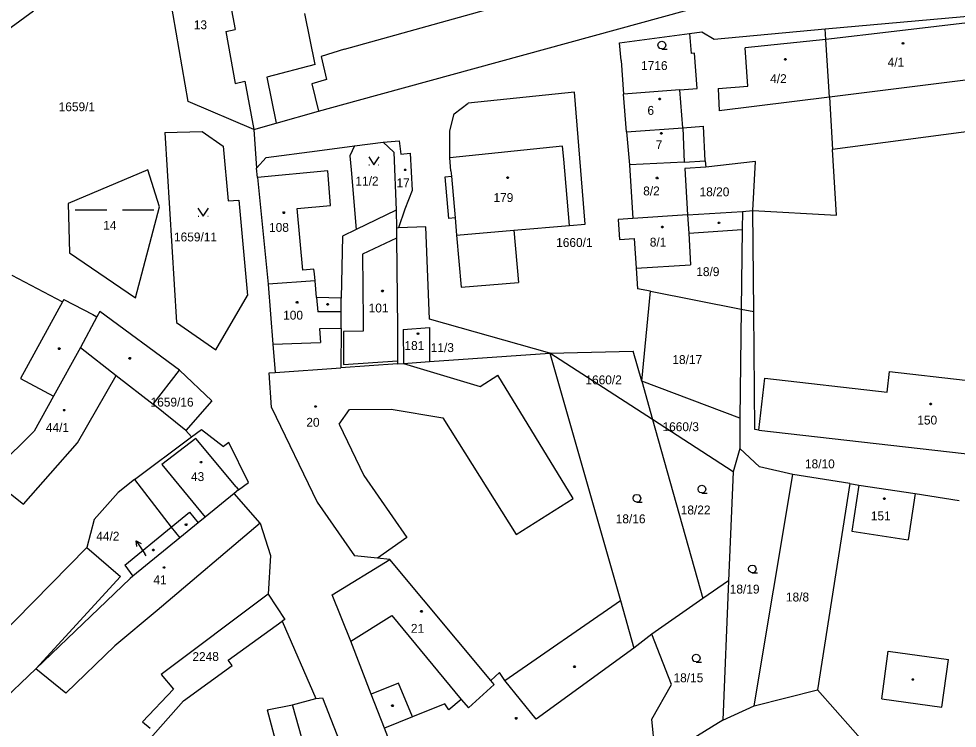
# Model space of a CAD drawing. Extents: x -802857 to -799647, y -1020285 to -1015884.
# Drawn here: x -801501.8 to -801322.5, y -1017775.9 to -1017640.2 of the extents above; entities that cross this region are included whole.
import ezdxf

# ---------------------------------------------------------------- set-up
doc = ezdxf.new("R2010")
doc.units = 0
for name, color, linetype in [('Default', 7, 'Continuous'), ('KN_HRANICE', 7, 'Continuous'), ('KN_KULTURY', 7, 'Continuous'), ('KN_PARCELY', 7, 'Continuous'), ('KN_SLUCKY', 7, 'Continuous')]:
    doc.layers.add(name, color=color, linetype=linetype)

# ---------------------------------------------------------------- blocks, each defined once
blk = doc.blocks.new('304')
at = {"layer": 'Default'}
blk.add_lwpolyline([(0, 0), (-0.38, 0.1), (-0.65, 0.37), (-0.75, 0.74), (-0.65, 1.11), (-0.38, 1.38), (-0.01, 1.48), (0.36, 1.38), (0.63, 1.11), (0.73, 0.73), (0.63, 0.35), (0.36, 0.08), (-0.02, -0.02), (0.98, -0.02)], dxfattribs=at)
blk = doc.blocks.new('314')
at = {"layer": 'Default'}
for p, q in [((-0.95, 0), (-0.85, 0)), ((0.85, 0), (0.95, 0))]:
    blk.add_line(p, q, dxfattribs=at)
blk.add_lwpolyline([(-1, 1.5), (0, 0), (1, 1.5)], dxfattribs=at)
blk = doc.blocks.new('NAHRADNI_SYMBOL')
at = {"layer": 'Default'}
blk.add_lwpolyline([(0.09, 0.15), (0.18, 0), (0.09, -0.15), (-0.09, -0.15), (-0.18, 0), (-0.09, 0.15), (0.09, 0.15)], dxfattribs=at)
blk = doc.blocks.new('803')
at = {"layer": 'Default'}
for p, q in [((-7.5, 0), (-1.5, 0)), ((1.5, 0), (7.5, 0))]:
    blk.add_line(p, q, dxfattribs=at)
blk = doc.blocks.new('10292')
at = {"layer": 'Default'}
blk.add_line((0, 3), (0, 0), dxfattribs=at)
blk.add_lwpolyline([(-0.5, 2), (0, 3), (0.5, 2)], dxfattribs=at)
blk = doc.blocks.new('402')
at = {"layer": 'Default'}
blk.add_lwpolyline([(0.09, 0.15), (0.18, 0), (0.09, -0.15), (-0.09, -0.15), (-0.18, 0), (-0.09, 0.15), (0.09, 0.15)], dxfattribs=at)

msp = doc.modelspace()

# ---------------------------------------------------------------- linework, layer by layer
at = {"layer": 'KN_HRANICE'}
for p, q in [((-801439.56, -1017646.05), (-801339.49, -1017618.1)), ((-801464.55, -1017620.59), (-801460.47, -1017642.27)), ((-801469.47, -1017656.08), (-801475.13, -1017623.23)), ((-801436.88, -1017655.78), (-801344.28, -1017630.37)), ((-801499.03, -1017638.78), (-801510.49, -1017647.16)), ((-801445.17, -1017648.98), (-801447.15, -1017639.26)), ((-801347.72, -1017642.2), (-801317.19, -1017639.44)), ((-801368.91, -1017644.12), (-801347.72, -1017642.2)), ((-801347.58, -1017644.22), (-801347.72, -1017642.2)), ((-801462.26, -1017642.67), (-801460.47, -1017642.27)), ((-801462.26, -1017642.67), (-801460.46, -1017652.61)), ((-801387, -1017644.83), (-801373.65, -1017643.04)), ((-801373.65, -1017643.04), (-801371.28, -1017642.72)), ((-801373.65, -1017643.04), (-801373.36, -1017646.87)), ((-801371.28, -1017642.72), (-801368.91, -1017644.12)), ((-801386.74, -1017648.25), (-801387, -1017644.83)), ((-801346.88, -1017655.22), (-801347.58, -1017644.22)), ((-801439.56, -1017646.05), (-801444.04, -1017647.45)), ((-801444.04, -1017647.45), (-801443.02, -1017651.83)), ((-801372.67, -1017646.8), (-801373.36, -1017646.87)), ((-801372.17, -1017653.55), (-801372.67, -1017646.8)), ((-801445.17, -1017648.98), (-801454.4, -1017651.38)), ((-801386.74, -1017648.25), (-801386.24, -1017654.63)), ((-801460.46, -1017652.61), (-801458.6, -1017652.2)), ((-801458.6, -1017652.2), (-801456.87, -1017661.39)), ((-801454.4, -1017651.38), (-801452.65, -1017660.21)), ((-801443.02, -1017651.83), (-801445.83, -1017652.69)), ((-801445.83, -1017652.69), (-801444.54, -1017657.93)), ((-801395.62, -1017654.26), (-801415.94, -1017656.38)), ((-801393.58, -1017679.48), (-801395.62, -1017654.26)), ((-801375.49, -1017653.85), (-801386.24, -1017654.63)), ((-801385.72, -1017661.85), (-801386.24, -1017654.63)), ((-801375.49, -1017653.85), (-801372.17, -1017653.55)), ((-801374.94, -1017661.08), (-801375.49, -1017653.85)), ((-801456.87, -1017661.39), (-801469.47, -1017656.08)), ((-801444.54, -1017657.93), (-801436.88, -1017655.78)), ((-801418.65, -1017658.44), (-801415.94, -1017656.38)), ((-801346.88, -1017655.22), (-801346.31, -1017665.23)), ((-801452.65, -1017660.21), (-801444.54, -1017657.93)), ((-801419.45, -1017661.66), (-801418.65, -1017658.44)), ((-801473.9, -1017661.96), (-801466.75, -1017661.81)), ((-801466.75, -1017661.81), (-801462.75, -1017664.58)), ((-801456.87, -1017661.39), (-801452.65, -1017660.21)), ((-801456.87, -1017661.39), (-801456.38, -1017668.8)), ((-801419.44, -1017665.46), (-801419.45, -1017661.66)), ((-801385.72, -1017661.85), (-801374.94, -1017661.08)), ((-801385.72, -1017661.85), (-801385.15, -1017668.16)), ((-801374.94, -1017661.08), (-801371.01, -1017660.78)), ((-801370.64, -1017667.41), (-801371.01, -1017660.78)), ((-801314.72, -1017661.03), (-801346.31, -1017665.23)), ((-801473.9, -1017661.96), (-801471.67, -1017698.28)), ((-801432.19, -1017663.81), (-801429.11, -1017663.56)), ((-801429.11, -1017663.56), (-801428.81, -1017666.12)), ((-801462.75, -1017664.58), (-801461.83, -1017675.05)), ((-801454.57, -1017666.75), (-801444.82, -1017665.47)), ((-801444.82, -1017665.47), (-801437.64, -1017664.53)), ((-801437.64, -1017664.53), (-801438.53, -1017666.45)), ((-801437.64, -1017664.53), (-801432.19, -1017663.81)), ((-801432.19, -1017663.81), (-801430.14, -1017665.75)), ((-801419.44, -1017666.81), (-801419.44, -1017665.46)), ((-801345.56, -1017677.77), (-801346.31, -1017665.23)), ((-801456.38, -1017668.8), (-801454.57, -1017666.75)), ((-801438.53, -1017666.45), (-801438.3, -1017669.15)), ((-801430.14, -1017665.75), (-801429.73, -1017676.83)), ((-801428.81, -1017666.12), (-801427.01, -1017665.96)), ((-801427.01, -1017665.96), (-801426.65, -1017673.07)), ((-801419.23, -1017669.3), (-801419.44, -1017666.81)), ((-801477.13, -1017669.12), (-801492.36, -1017675.58)), ((-801474.9, -1017676.19), (-801477.13, -1017669.12)), ((-801456.2, -1017670.59), (-801456.38, -1017668.8)), ((-801374.65, -1017667.67), (-801385.15, -1017668.16)), ((-801385.15, -1017668.16), (-801384.5, -1017678.44)), ((-801374.65, -1017667.67), (-801370.64, -1017667.41)), ((-801370.54, -1017668.61), (-801374.57, -1017668.87)), ((-801374.57, -1017668.87), (-801374.01, -1017677.75)), ((-801370.64, -1017667.41), (-801370.54, -1017668.61)), ((-801361.03, -1017667.51), (-801370.54, -1017668.61)), ((-801361.54, -1017676.89), (-801361.03, -1017667.51)), ((-801456.2, -1017670.59), (-801454.16, -1017690.99)), ((-801438.3, -1017669.15), (-801437.35, -1017680.56)), ((-801420.34, -1017670.46), (-801419.14, -1017670.36)), ((-801419.66, -1017678.43), (-801420.34, -1017670.46)), ((-801419.23, -1017669.3), (-801419.14, -1017670.36)), ((-801426.65, -1017673.07), (-801428.05, -1017676.64)), ((-801492.36, -1017675.58), (-801492.13, -1017684.97)), ((-801479.51, -1017693.58), (-801474.9, -1017676.19)), ((-801461.83, -1017675.05), (-801459.74, -1017674.9)), ((-801459.74, -1017674.9), (-801458.13, -1017693.12)), ((-801429.73, -1017676.83), (-801437.35, -1017680.56)), ((-801429.73, -1017676.83), (-801429.65, -1017680.25)), ((-801428.05, -1017676.64), (-801429.23, -1017680.23)), ((-801374.01, -1017677.75), (-801384.5, -1017678.44)), ((-801374.01, -1017677.75), (-801363.53, -1017677.06)), ((-801363.53, -1017677.06), (-801361.54, -1017676.89)), ((-801361.37, -1017696.22), (-801361.54, -1017676.89)), ((-801361.54, -1017676.89), (-801345.56, -1017677.77)), ((-801418.46, -1017678.33), (-801419.66, -1017678.43)), ((-801418.46, -1017678.33), (-801418.18, -1017681.62)), ((-801407.22, -1017680.67), (-801396.57, -1017679.74)), ((-801396.57, -1017679.74), (-801393.58, -1017679.48)), ((-801384.5, -1017678.44), (-801387.29, -1017678.62)), ((-801387.29, -1017678.62), (-801387.04, -1017682.41)), ((-801437.35, -1017680.56), (-801439.98, -1017681.83)), ((-801429.23, -1017680.23), (-801429.65, -1017680.25)), ((-801429.65, -1017680.25), (-801429.62, -1017682.21)), ((-801424.02, -1017680.04), (-801429.23, -1017680.23)), ((-801423.35, -1017697.69), (-801424.02, -1017680.04)), ((-801418.18, -1017681.62), (-801417.31, -1017691.58)), ((-801407.22, -1017680.67), (-801406.35, -1017690.63)), ((-801373.8, -1017681.22), (-801363.58, -1017680.51)), ((-801373.8, -1017681.22), (-801373.44, -1017687.26)), ((-801363.58, -1017680.51), (-801363.78, -1017695.75)), ((-801439.98, -1017681.83), (-801440.22, -1017693.66)), ((-801429.62, -1017682.21), (-801429.47, -1017699.34)), ((-801387.04, -1017682.41), (-801384.25, -1017682.23)), ((-801384.25, -1017682.23), (-801383.87, -1017687.92)), ((-801492.13, -1017684.97), (-801479.51, -1017693.58)), ((-801383.87, -1017687.92), (-801373.44, -1017687.26)), ((-801383.87, -1017687.92), (-801383.61, -1017691.85)), ((-801503.16, -1017689.24), (-801493.48, -1017694.38)), ((-801445.17, -1017690.35), (-801454.16, -1017690.99)), ((-801444.9, -1017693.53), (-801445.17, -1017690.35)), ((-801417.31, -1017691.58), (-801406.35, -1017690.63)), ((-801454.16, -1017690.99), (-801453.25, -1017702.44)), ((-801381.12, -1017692.34), (-801383.61, -1017691.85)), ((-801382.78, -1017709.52), (-801381.12, -1017692.34)), ((-801381.12, -1017692.34), (-801363.78, -1017695.75)), ((-801493.2, -1017693.88), (-801493.48, -1017694.38)), ((-801493.2, -1017693.88), (-801487.66, -1017696.81)), ((-801464.13, -1017703.51), (-801458.13, -1017693.12)), ((-801444.9, -1017693.53), (-801444.66, -1017696.24)), ((-801440.21, -1017696.24), (-801440.22, -1017693.66)), ((-801363.78, -1017695.75), (-801364.05, -1017716.58)), ((-801363.78, -1017695.75), (-801361.37, -1017696.22)), ((-801486.87, -1017697.21), (-801490.05, -1017703.09)), ((-801487.66, -1017696.81), (-801486.87, -1017697.21)), ((-801486.33, -1017696.21), (-801486.87, -1017697.21)), ((-801471.12, -1017707.39), (-801486.33, -1017696.21)), ((-801440.21, -1017696.24), (-801444.66, -1017696.24)), ((-801440.22, -1017698), (-801440.21, -1017696.24)), ((-801400.33, -1017704.19), (-801423.35, -1017697.69)), ((-801361.18, -1017718.78), (-801361.37, -1017696.22)), ((-801471.67, -1017698.28), (-801464.13, -1017703.51)), ((-801440.23, -1017699.44), (-801440.25, -1017706.98)), ((-801440.23, -1017699.44), (-801440.22, -1017698)), ((-801429.47, -1017699.34), (-801429.43, -1017705.64)), ((-801428.36, -1017699.63), (-801423.34, -1017699.29)), ((-801423.34, -1017699.29), (-801423.32, -1017705.79)), ((-801428.36, -1017699.63), (-801428.32, -1017706.16)), ((-801490.05, -1017703.09), (-801495.16, -1017712.38)), ((-801453.25, -1017702.44), (-801452.8, -1017707.85)), ((-801423.32, -1017705.79), (-801400.33, -1017704.19)), ((-801400.33, -1017704.19), (-801384.4, -1017703.77)), ((-801400.33, -1017704.19), (-801386.84, -1017751.44)), ((-801380.71, -1017716.88), (-801400.33, -1017704.19)), ((-801382.78, -1017709.52), (-801384.4, -1017703.77)), ((-801429.43, -1017706.24), (-801440.25, -1017706.98)), ((-801429.43, -1017705.64), (-801429.43, -1017706.24)), ((-801429.43, -1017706.24), (-801428.32, -1017706.16)), ((-801428.32, -1017706.16), (-801423.32, -1017705.79)), ((-801476.12, -1017713.95), (-801471.12, -1017707.39)), ((-801471.12, -1017707.39), (-801464.92, -1017713.27)), ((-801453.96, -1017707.92), (-801452.8, -1017707.85)), ((-801453.53, -1017714.55), (-801453.96, -1017707.92)), ((-801452.8, -1017707.85), (-801440.25, -1017706.98)), ((-801364.05, -1017716.58), (-801382.78, -1017709.52)), ((-801382.78, -1017709.52), (-801380.71, -1017716.88)), ((-801495.16, -1017712.38), (-801498.85, -1017719.1)), ((-801469.89, -1017718.97), (-801476.12, -1017713.95)), ((-801464.92, -1017713.27), (-801469.89, -1017718.97)), ((-801453.53, -1017714.55), (-801444.8, -1017732.63)), ((-801365.33, -1017726.83), (-801380.71, -1017716.88)), ((-801380.71, -1017716.88), (-801371.09, -1017751.09)), ((-801364.05, -1017716.58), (-801364.06, -1017722.39)), ((-801498.85, -1017719.1), (-801507.61, -1017727.7)), ((-801469.89, -1017718.97), (-801468.81, -1017720.17)), ((-801468.81, -1017720.17), (-801466.92, -1017718.75)), ((-801466.92, -1017718.75), (-801462.68, -1017722.04)), ((-801360.4, -1017718.86), (-801361.18, -1017718.78)), ((-801360.4, -1017718.86), (-801315.22, -1017724.02)), ((-801479.69, -1017728.34), (-801468.81, -1017720.17)), ((-801461.67, -1017721.24), (-801462.68, -1017722.04)), ((-801457.95, -1017728.92), (-801461.67, -1017721.24)), ((-801364.06, -1017722.39), (-801365.33, -1017726.83)), ((-801360.25, -1017725.9), (-801364.06, -1017722.39)), ((-801353.93, -1017727.34), (-801360.25, -1017725.9)), ((-801365.33, -1017726.83), (-801366.23, -1017747.72)), ((-801361.29, -1017771.58), (-801353.93, -1017727.34)), ((-801342.99, -1017729.09), (-801353.93, -1017727.34)), ((-801479.69, -1017728.34), (-801482.8, -1017730.8)), ((-801479.69, -1017728.34), (-801472.69, -1017737.41)), ((-801459.8, -1017730.31), (-801457.95, -1017728.92)), ((-801342.99, -1017729.09), (-801349.19, -1017768.52)), ((-801342.99, -1017729.09), (-801341.32, -1017729.38)), ((-801341.32, -1017729.38), (-801330.53, -1017731.02)), ((-801482.8, -1017730.8), (-801487.38, -1017735.95)), ((-801460.64, -1017731), (-801466.21, -1017735.54)), ((-801459.8, -1017730.31), (-801460.64, -1017731)), ((-801455.66, -1017736.67), (-801460.64, -1017731)), ((-801330.53, -1017731.02), (-801322.14, -1017732.32)), ((-801444.8, -1017732.63), (-801437.69, -1017742.9)), ((-801487.38, -1017735.95), (-801488.83, -1017741.31)), ((-801467.55, -1017736.63), (-801471.07, -1017739.5)), ((-801466.21, -1017735.54), (-801467.55, -1017736.63)), ((-801455.66, -1017736.67), (-801453.7, -1017742.86)), ((-801472.69, -1017737.41), (-801471.07, -1017739.5)), ((-801471.07, -1017739.5), (-801480.05, -1017746.82)), ((-801488.83, -1017741.31), (-801482.4, -1017746.87)), ((-801453.7, -1017742.86), (-801454.14, -1017750.26)), ((-801441.93, -1017750.37), (-801430.91, -1017743.61)), ((-801433.27, -1017743.36), (-801437.69, -1017742.9)), ((-801430.91, -1017743.61), (-801433.27, -1017743.36)), ((-801411.64, -1017766.72), (-801430.91, -1017743.61)), ((-801482.4, -1017746.87), (-801498.56, -1017764.53)), ((-801480.55, -1017747.22), (-801498.56, -1017764.53)), ((-801480.05, -1017746.82), (-801480.55, -1017747.22)), ((-801366.23, -1017747.72), (-801371.09, -1017751.09)), ((-801366.23, -1017747.72), (-801367.27, -1017774.31)), ((-801454.14, -1017750.26), (-801474.58, -1017765.6)), ((-801454.14, -1017750.26), (-801451, -1017755.07)), ((-801438.38, -1017759.22), (-801441.93, -1017750.37)), ((-801386.84, -1017751.44), (-801384.3, -1017760.57)), ((-801371.09, -1017751.09), (-801380.85, -1017757.91)), ((-801451, -1017755.07), (-801451.46, -1017755.42)), ((-801451.46, -1017755.42), (-801445.03, -1017770.19)), ((-801380.85, -1017757.91), (-801384.3, -1017760.57)), ((-801377.08, -1017767.48), (-801380.85, -1017757.91)), ((-801434.46, -1017769.34), (-801438.38, -1017759.22)), ((-801384.3, -1017760.57), (-801402.96, -1017774.15)), ((-801498.56, -1017764.53), (-801505.81, -1017771.41)), ((-801474.58, -1017765.6), (-801472.28, -1017768.42)), ((-801409.95, -1017765.22), (-801411.64, -1017766.72)), ((-801408.92, -1017766.74), (-801409.95, -1017765.22)), ((-801415.89, -1017771.96), (-801410.96, -1017767.53)), ((-801410.96, -1017767.53), (-801411.64, -1017766.72)), ((-801402.96, -1017774.15), (-801408.92, -1017766.74)), ((-801380.85, -1017774.15), (-801377.08, -1017767.48)), ((-801472.28, -1017768.42), (-801478.17, -1017774.62)), ((-801431.94, -1017775.86), (-801434.46, -1017769.34)), ((-801361.29, -1017771.58), (-801349.19, -1017768.52)), ((-801338.75, -1017780.31), (-801349.19, -1017768.52)), ((-801449.49, -1017771.37), (-801445.03, -1017770.19)), ((-801445.03, -1017770.19), (-801443.81, -1017770.05)), ((-801443.81, -1017770.05), (-801439.99, -1017779.67)), ((-801420.38, -1017771.18), (-801426.59, -1017773.69)), ((-801419.61, -1017772.37), (-801420.38, -1017771.18)), ((-801417.3, -1017770.37), (-801419.61, -1017772.37)), ((-801417.3, -1017770.37), (-801415.89, -1017771.96)), ((-801454.34, -1017772.35), (-801449.49, -1017771.37)), ((-801454.34, -1017772.35), (-801451.15, -1017784.39)), ((-801367.27, -1017774.31), (-801361.29, -1017771.58)), ((-801478.17, -1017774.62), (-801476.71, -1017775.88)), ((-801426.59, -1017773.69), (-801431.94, -1017775.86)), ((-801380.06, -1017782.2), (-801380.85, -1017774.15)), ((-801367.27, -1017774.31), (-801380.06, -1017782.2)), ((-801428.76, -1017784.1), (-801431.94, -1017775.86))]:
    msp.add_line(p, q, dxfattribs=at)
msp.add_lwpolyline([(-801480.11, -1017781.68), (-801470.32, -1017770.64), (-801461.06, -1017763.9), (-801461.81, -1017762.88), (-801451.46, -1017755.42)], dxfattribs=at)
at = {"layer": 'KN_PARCELY'}
msp.add_line((-801477.47, -1017742.93), (-801477.73, -1017742.53), dxfattribs=at)
at = {"layer": 'KN_SLUCKY'}
for p, q in [((-801317.18, -1017640.62), (-801334.53, -1017642.7)), ((-801334.53, -1017642.7), (-801347.58, -1017644.22)), ((-801347.58, -1017644.22), (-801363.02, -1017645.81)), ((-801362.49, -1017653.14), (-801363.02, -1017645.81)), ((-801315.88, -1017651.33), (-801346.88, -1017655.22)), ((-801368.2, -1017653.58), (-801362.49, -1017653.14)), ((-801368.2, -1017653.58), (-801367.99, -1017657.86)), ((-801346.88, -1017655.22), (-801367.99, -1017657.86)), ((-801374.94, -1017661.08), (-801374.65, -1017667.67)), ((-801397.89, -1017664.58), (-801419.44, -1017666.81)), ((-801397.68, -1017667.07), (-801397.89, -1017664.58)), ((-801396.57, -1017679.74), (-801397.68, -1017667.07)), ((-801442.79, -1017669.32), (-801456.2, -1017670.59)), ((-801442.23, -1017675.92), (-801442.79, -1017669.32)), ((-801419.14, -1017670.36), (-801418.46, -1017678.33)), ((-801448.61, -1017676.52), (-801442.23, -1017675.92)), ((-801447.51, -1017688.29), (-801448.61, -1017676.52)), ((-801374.01, -1017677.75), (-801373.8, -1017681.22)), ((-801363.53, -1017677.06), (-801363.58, -1017680.51)), ((-801418.18, -1017681.62), (-801407.22, -1017680.67)), ((-801429.62, -1017682.21), (-801436.16, -1017685.24)), ((-801436.16, -1017685.24), (-801436.01, -1017697.99)), ((-801445.41, -1017688.09), (-801447.51, -1017688.29)), ((-801445.33, -1017688.99), (-801445.41, -1017688.09)), ((-801445.17, -1017690.35), (-801445.33, -1017688.99)), ((-801440.22, -1017693.66), (-801444.9, -1017693.53)), ((-801493.48, -1017694.38), (-801501.51, -1017709.02)), ((-801440.23, -1017699.44), (-801444.38, -1017699.5)), ((-801444.38, -1017699.5), (-801444.15, -1017702.13)), ((-801436.01, -1017697.99), (-801435.99, -1017699.99)), ((-801435.99, -1017699.99), (-801439.78, -1017700.01)), ((-801439.78, -1017700.01), (-801439.74, -1017706.34)), ((-801490.05, -1017703.09), (-801483.23, -1017708.46)), ((-801453.25, -1017702.44), (-801444.15, -1017702.13)), ((-801439.74, -1017706.34), (-801429.43, -1017705.64)), ((-801428.32, -1017706.16), (-801413.65, -1017710.55)), ((-801490.57, -1017721.33), (-801483.23, -1017708.46)), ((-801483.23, -1017708.46), (-801476.12, -1017713.95)), ((-801413.65, -1017710.55), (-801410.25, -1017708.4)), ((-801395.86, -1017731.97), (-801410.25, -1017708.4)), ((-801335.87, -1017711.65), (-801335.42, -1017707.67)), ((-801335.42, -1017707.67), (-801320.96, -1017709.32)), ((-801501.51, -1017709.02), (-801495.16, -1017712.38)), ((-801360.4, -1017718.86), (-801359.27, -1017708.97)), ((-801359.27, -1017708.97), (-801335.87, -1017711.65)), ((-801440.62, -1017717.72), (-801438.64, -1017714.97)), ((-801438.64, -1017714.97), (-801430.65, -1017714.89)), ((-801430.65, -1017714.89), (-801420.77, -1017716.55)), ((-801420.77, -1017716.55), (-801406.77, -1017738.86)), ((-801440.62, -1017717.72), (-801435.87, -1017727.56)), ((-801468, -1017720.51), (-801474.46, -1017725.46)), ((-801460.29, -1017729.75), (-801468, -1017720.51)), ((-801500.92, -1017733.04), (-801490.57, -1017721.33)), ((-801474.46, -1017725.46), (-801466.21, -1017735.54)), ((-801507.61, -1017727.7), (-801500.92, -1017733.04)), ((-801435.87, -1017727.56), (-801427.66, -1017739.42)), ((-801460.29, -1017729.75), (-801459.8, -1017730.31)), ((-801341.32, -1017729.38), (-801342.64, -1017738.21)), ((-801330.53, -1017731.02), (-801331.85, -1017739.85)), ((-801406.77, -1017738.86), (-801395.86, -1017731.97)), ((-801472.69, -1017737.41), (-801469.19, -1017734.55)), ((-801469.19, -1017734.55), (-801467.55, -1017736.63)), ((-801455.66, -1017736.67), (-801475.36, -1017753.35)), ((-801481.58, -1017744.68), (-801472.69, -1017737.41)), ((-801342.64, -1017738.21), (-801331.85, -1017739.85)), ((-801427.66, -1017739.42), (-801433.27, -1017743.36)), ((-801506.09, -1017758.92), (-801488.83, -1017741.31)), ((-801481.58, -1017744.68), (-801480.05, -1017746.82)), ((-801408.92, -1017766.74), (-801386.84, -1017751.44)), ((-801475.36, -1017753.35), (-801483.45, -1017760.14)), ((-801438.38, -1017759.22), (-801430.55, -1017754.32)), ((-801430.55, -1017754.32), (-801417.3, -1017770.37)), ((-801483.45, -1017760.14), (-801492.84, -1017769.18)), ((-801336.9, -1017770.22), (-801335.67, -1017761.12)), ((-801335.67, -1017761.12), (-801324.19, -1017762.71)), ((-801325.42, -1017771.81), (-801324.19, -1017762.71)), ((-801492.84, -1017769.18), (-801498.56, -1017764.53)), ((-801429.27, -1017767.23), (-801434.46, -1017769.34)), ((-801426.59, -1017773.69), (-801429.27, -1017767.23)), ((-801336.9, -1017770.22), (-801325.42, -1017771.81)), ((-801446.22, -1017783.09), (-801449.49, -1017771.37))]:
    msp.add_line(p, q, dxfattribs=at)

# ---------------------------------------------------------------- block references
at = {"layer": 'KN_KULTURY'}
for name, p in [('304', (-801378.93, -1017646.01)), ('402', (-801332.86, -1017644.95)), ('402', (-801355.34, -1017648.02)), ('NAHRADNI_SYMBOL', (-801379.35, -1017655.58)), ('402', (-801379.04, -1017662.16)), ('314', (-801433.95, -1017668.16)), ('NAHRADNI_SYMBOL', (-801427.98, -1017669.12)), ('402', (-801408.4, -1017670.64)), ('402', (-801379.85, -1017670.67)), ('803', (-801483.51, -1017676.77)), ('314', (-801466.57, -1017677.96)), ('402', (-801451.17, -1017677.33)), ('402', (-801368.03, -1017679.26)), ('402', (-801378.85, -1017680.06)), ('402', (-801432.33, -1017692.29)), ('402', (-801448.64, -1017694.44)), ('402', (-801442.8, -1017694.84)), ('402', (-801425.54, -1017700.45)), ('402', (-801494.08, -1017703.33)), ('402', (-801480.6, -1017705.17)), ('402', (-801327.58, -1017713.87)), ('402', (-801493.14, -1017715.06)), ('402', (-801445.11, -1017714.36)), ('402', (-801466.98, -1017725.01)), ('304', (-801371.28, -1017730.89)), ('304', (-801383.7, -1017732.65)), ('402', (-801336.43, -1017731.99)), ('402', (-801469.84, -1017736.96)), ('402', (-801476.11, -1017741.82)), ('402', (-801474.04, -1017745.14)), ('304', (-801361.65, -1017746.16)), ('402', (-801424.88, -1017753.52)), ('304', (-801372.36, -1017763.19)), ('402', (-801395.63, -1017764.09)), ('402', (-801330.98, -1017766.55)), ('402', (-801430.42, -1017771.55)), ('NAHRADNI_SYMBOL', (-801406.77, -1017773.98))]:
    msp.add_blockref(name, p, dxfattribs=at)
at = {"layer": 'KN_PARCELY', "rotation": 33.116960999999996}
msp.add_blockref('10292', (-801477.73, -1017742.53), dxfattribs=at)

# ---------------------------------------------------------------- texts
at = {"layer": 'KN_PARCELY'}
for s, height, p in [('13', 1.7, (-801468.37, -1017642.25)), ('4/1', 1.7, (-801335.79, -1017649.39)), ('1716', 1.7, (-801382.91, -1017650.05)), ('4/2', 1.7, (-801358.24, -1017652.55)), ('1659/1', 1.7, (-801494.19, -1017657.92)), ('6', 1.7, (-801381.69, -1017658.61)), ('7', 1.7, (-801380.1, -1017665.17)), ('11/2', 1.7, (-801437.49, -1017672.12)), ('17', 1.7, (-801429.64, -1017672.46)), ('8/2', 1.7, (-801382.5, -1017674.01)), ('18/20', 1.7, (-801371.73, -1017674.18)), ('179', 1.7, (-801411.11, -1017675.28)), ('14', 1.7, (-801485.68, -1017680.58)), ('108', 1.7, (-801453.99, -1017680.98)), ('1659/11', 1.7, (-801472.15, -1017682.81)), ('1660/1', 1.7, (-801399.13, -1017683.87)), ('8/1', 1.7, (-801381.24, -1017683.8)), ('18/9', 1.7, (-801372.36, -1017689.44)), ('101', 1.7, (-801434.96, -1017696.39)), ('100', 1.7, (-801451.3, -1017697.76)), ('181', 1.7, (-801428.12, -1017703.56)), ('11/3', 1.7, (-801423.09, -1017703.96)), ('18/17', 1.7, (-801376.93, -1017706.25)), ('1660/2', 1.7, (-801393.54, -1017710.13)), ('1659/16', 1.7, (-801476.63, -1017714.38)), ('44/1', 1.7, (-801496.64, -1017719.24)), ('20', 1.7, (-801446.87, -1017718.24)), ('1660/3', 1.7, (-801378.81, -1017719.08)), ('150', 1.7, (-801330.13, -1017717.81)), ('18/10', 1.7, (-801351.59, -1017726.18)), ('43', 1.7, (-801468.91, -1017728.62)), ('18/22', 1.7, (-801375.33, -1017735)), ('18/16', 1.7, (-801387.75, -1017736.69)), ('151', 1.7, (-801339.01, -1017736.13)), ('44/2', 1.7, (-801487.01, -1017740.02)), ('44/2', 0.1, (-801477.67, -1017742.93)), ('41', 1.7, (-801476.09, -1017748.34)), ('18/19', 1.7, (-801365.96, -1017750.12)), ('18/8', 1.7, (-801355.23, -1017751.64)), ('21', 1.7, (-801426.89, -1017757.63)), ('18/15', 1.7, (-801376.71, -1017767.08))]:
    msp.add_text(s, height=height, dxfattribs=at).set_placement(p)
msp.add_text('2248', height=1.7, rotation=0.458, dxfattribs=at).set_placement((-801468.63, -1017763.04))

doc.saveas('drawing.dxf')
